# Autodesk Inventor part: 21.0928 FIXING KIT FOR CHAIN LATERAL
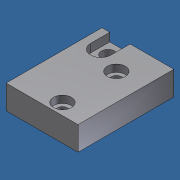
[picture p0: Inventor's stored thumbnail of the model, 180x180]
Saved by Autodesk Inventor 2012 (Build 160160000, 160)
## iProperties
Created: 2013-11
Part Number: 21.0928 FIXING KIT FOR CHAIN LATERAL
Material: Default
Document SubType Name: Modeling
Designer: Admin
Density: 1 g/cm^3
Author: Admin
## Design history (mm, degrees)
sketch "Sketch1"
  geometry: L1 (-30, 40)-(30, 40); L2 (30, 40)-(30, -40); L3 (30, -40)-(-30, -40); L4 (-30, -40)-(-30, 40); C1 r 4.25 at (7.5, -30.5); C2 r 4.25 at (7.5, 14.5); C3 r 5.5 at (-15, 30); 3 further points
  constraints: 8 end point, 3 centre point, 2 midpoint, 2 parallel, 2 vertical alignment, 1 horizontal, 1 horizontal alignment, 1 perpendicular
  dimensions: "d0" = 60 distance between parallel lines of L2 L4; "d1" = 80 distance of L3.end L1.start; "d2" = 8.5 diameter of C1; "d3" = 8.5 diameter of C2; "d4" = 11 diameter of C3; "d5" = 22.5 distance from line of C2.centre L2; "d6" = 9.5 distance from line of C1.centre L3; "d7" = 45 distance of C1.centre C2.centre; "d8" = 10 distance from line of C3.centre L1; "d9" = 15 distance from line of C3.centre L4
extrude "Extrusion1" new body sketch "Sketch1" stored distance "d10" = 20; taper "d11" = 0 deg
sketch "Sketch2"
  geometry: C1 r 4.25 at (7.5, 14.5) reference; C2 r 4.25 at (7.5, -30.5) reference; C3 r 7.5 at (7.5, -30.5); C4 r 7.5 at (7.5, 14.5); 1 further point
  constraints: 2 centre point, 2 coincident
  dimensions: "d12" = 15 diameter of C3; "d13" = 15 diameter of C4
extrude "Extrusion2" cut sketch "Sketch2" distance "d14" = 6; taper "d15" = 0 deg
sketch "Sketch3"
  geometry: L1 (-30, 40)-(30, 40) reference; L2 (-23.5, 24)-(-23.5, 40); L3 (-6.5, 24)-(-6.5, 40); C1 r 5.5 at (-15, 30) reference; A1 r 8.5 centre (-15, 24) between (-23.5, 24) and (-6.5, 24); 1 further point
  constraints: 4 end point, 2 perpendicular, 2 point on circle, 2 point on line, 2 tangent, 1 centre point, 1 vertical alignment
  dimensions: "d16" = 8.5 radius of A1; "d17" = 16 distance from line of A1.centre L1
extrude "Extrusion3" cut sketch "Sketch3" distance "d18" = 7; taper "d19" = 0 deg
mirror "Mirror1"
body "Solid1"
